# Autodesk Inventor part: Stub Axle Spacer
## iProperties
Shininess: 100.0
Angle Display Precision: 2
Document Length Units: 11269
Document Angle Units: 11279
Document Time Units: 11290
Document Mass Units: 11283
Document Length Units Precision: 3
Document Angle Units Precision: 2
Compacted: True
Created: 2001-08
Part Number: Stub Axle Spacer
Document SubType Name: Modeling
Designer: Martin Budgell
Density: 0.0
Volumn: 0.0
Area: 0.0
PropertySet Name: Model Information
Control State: 0
Master: False
Checked Out: False
Author: Martin Budgell
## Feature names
1. Extrusion1
2. Extrusion2
3. Chamfer1
4. Fillet1
